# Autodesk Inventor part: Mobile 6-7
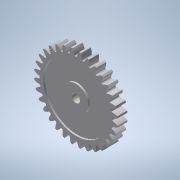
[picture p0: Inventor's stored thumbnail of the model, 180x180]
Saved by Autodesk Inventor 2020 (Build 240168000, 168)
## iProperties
Created: 2002-01
Part Number: Mobile 6-7
Material: Plastique ABS
Document SubType Name: Modélisation
Designer: Philippe
Mass: 0.0770357 g
Surface Area: 2.62235 cm^2
Volume: 0.0726752 cm^3
Density: 1.06 g/cm^3
Appearance: Plastique (Blanc)
Shininess: 21.0
Angle Display Precision: 2
Document Length Units: 11269
Document Angle Units: 11279
Document Time Units: 11290
Document Mass Units: 11283
Document Length Units Precision: 3
Document Angle Units Precision: 2
Density: 0.0
Volumn: 0.0
Area: 0.0
PropertySet Name: Model Information
Control State: 0
Master: False
Checked Out: False
Author: Philippe
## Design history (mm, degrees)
sketch "Esquisse1"
  geometry: L1 (0, 0)-(5, 0); L2 (5, 0)-(5, 1.2); L3 (5, 1.2)-(1.5, 1.2); L4 (1.5, 1.2)-(1.5, 3.4); L5 (1.5, 3.4)-(0, 3.4); L6 (0, 3.4)-(0, 0)
  constraints: 12 end point, 4 parallel, 1 horizontal, 1 perpendicular, 1 other
  dimensions: "d0" = 1.2 distance of L1.end L2.end; "d1" = 3.4 distance between parallel lines of L5 L1; "d2" = 3 diameter of L4.end L6; "d3" = 10 diameter of L2 L6
revolve "Révolution1" sketch "Esquisse1" stored, may be unused: angle "d4" = 90 deg
sketch "Esquisse2"
  geometry: C1 r 5 at (0, 0) reference; C2 r 0.5 at (0, 0)
  constraints: 1 centre point, 1 coincident
  dimensions: "d5" = 1 diameter of C2
extrude "Extrusion1" cut sketch "Esquisse2" extent not by distance; stored distance "d6" = 10; taper "d7" = 0 deg
node "Axe de construction1"
sketch "Esquisse6"
  geometry: C1 r 0.5 at (0, 0) reference; C2 r 1.5 at (0, 0); C3 r 3.9 at (0, 0)
  constraints: 2 centre point
  dimensions: "d32" = 3 diameter of C2; "d33" = 7.8 diameter of C3
extrude "Extrusion5" cut sketch "Esquisse6" distance "d34" = 0.2; taper "d35" = 0 deg
sketch "Esquisse7"
  geometry: C1 r 3.9 at (0, 0) reference; C2 r 1.5 at (0, 0) reference
extrude "Extrusion6" cut sketch "Esquisse7" distance "d36" = 0.2; taper "d37" = 0 deg
sketch "Esquisse8"
  geometry: L1 (0, 0)-(0, 5); C1 r 3.9 at (0, 0) reference; C2 r 4.7 at (0, 0); A1 r 5 centre (0, 0) between (-0.39, 4.985) and (0, 5) reference; A2 r 4.325 centre (0, 0) between (0.041, 4.325) and (-0.041, 4.325); A3 r 1.607 centre (-1.712, 4.071) between (-0.14, 4.404) and (-0.39, 4.985); A4 r 1.607 centre (1.712, 4.071) between (0.39, 4.985) and (0.14, 4.404); A5 r 0.1 centre (-0.042, 4.425) between (-0.14, 4.404) and (-0.041, 4.325); A6 r 0.1 centre (0.042, 4.425) between (0.041, 4.325) and (0.14, 4.404); A7 r 5 centre (0, 0) between (0.39, 4.985) and (-0.39, 4.985)
  constraints: 15 point on circle, 7 centre point, 4 tangent, 2 end point, 2 equal radius, 1 vertical
  dimensions: "d38" = 0.3 radial gap between concentric circles of C2 A1; "d39" = 0.375 radial gap between concentric circles of A2 C2; "d40" = 0.1 radius of A5
extrude "Extrusion7" cut sketch "Esquisse8" extent not by distance; stored distance "d41" = 10; taper "d42" = 0 deg
sketch "Esquisse11"
  geometry: A1 r 1.5 centre (0, 0) between (-0.602, 1.374) and (0.602, 1.374) reference; A2 r 0.825 centre (0, 0) between (0.068, 0.822) and (-0.068, 0.822); A3 r 0.41 centre (-0.585, 0.964) between (-0.176, 0.93) and (-0.602, 1.374); A4 r 0.41 centre (0.585, 0.964) between (0.602, 1.374) and (0.176, 0.93); A5 r 0.1 centre (-0.076, 0.922) between (-0.176, 0.93) and (-0.068, 0.822); A6 r 0.1 centre (0.076, 0.922) between (0.068, 0.822) and (0.176, 0.93); A7 r 1.5 centre (0, 0) between (0.602, 1.374) and (-0.602, 1.374)
  constraints: 14 point on circle, 6 centre point, 4 tangent, 1 equal radius
  dimensions: "d62" = 0.1 radius of A5
extrude "Extrusion10" cut sketch "Esquisse11" stored distance "d63" = 2.5; taper "d64" = 0 deg
pattern_circular "Réseau circulaire6" dims angle "d67" = 360 deg
node "Solide1"
node "Corps solides"
node "Corps surfaciques"
pattern_circular "Réseau circulaire4" dims angle "d45" = 360 deg
